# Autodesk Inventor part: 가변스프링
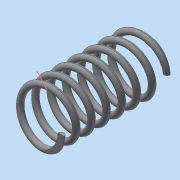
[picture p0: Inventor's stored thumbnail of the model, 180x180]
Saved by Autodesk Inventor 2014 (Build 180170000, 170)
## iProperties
Created: 2022-08
Part Number: 가변스프링
Material: 스테인레스 스틸
Document SubType Name: Sheet Metal
Designer: dg
Density: 8.08 g/cm^3
Sheet Metal Rule: Default_mm
Appearance: 반연마
Mass: 70.5056 g
Surface Area: 88.358 cm^2
Volume: 8.72595 cm^3
Author: dg
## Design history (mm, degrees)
sketch "스케치1"
  geometry: L1 (16, 0)-(0, 0); L2 (0, 0)-(0, 64); L3 (0, 64)-(16, 64); C1 r 2 at (16, 0)
  constraints: 6 end point, 1 centre point, 1 coincident, 1 horizontal, 1 parallel, 1 perpendicular, 1 vertical alignment
  dimensions: "d0" = 4 diameter of C1; "d1" = 32 diameter of L1.start L2; "d2" = 64 distance of L1.end L2.end (derived)
feature "코일1" pitch "d3" = 10; turns "d5" = 7; dims "d4" = 64 (= d2), "d6" = 0, angle "d7" = 90 deg, angle "d8" = 90 deg, "d9" = 0, "d10" = 0
node "작업 평면1"
feature "분할1"
feature "분할2"
node "솔리드1"
other parameters: "SeamGap" = 0.01, "d11" = 90 deg
